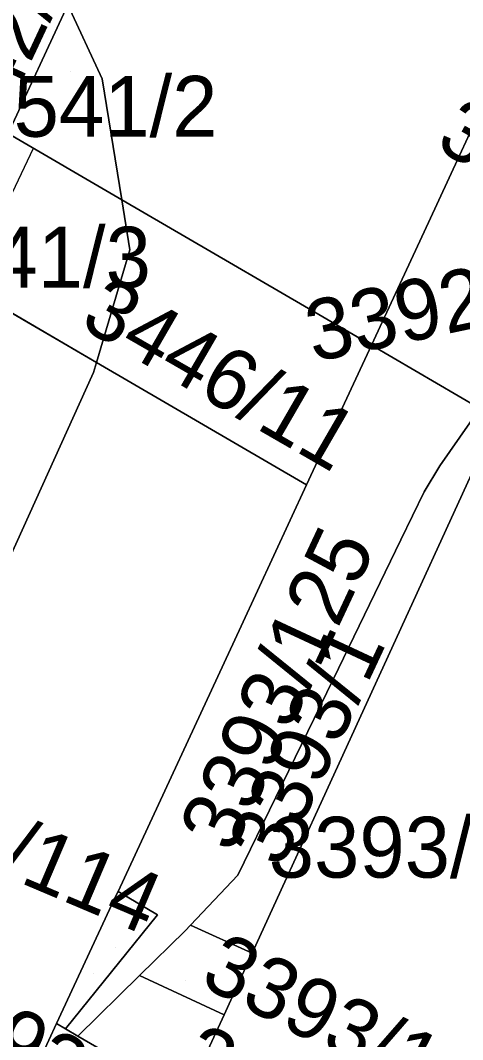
# Model space of a CAD drawing. Extents: x -262715 to -259381, y -1237238 to -1231182.
# Drawn here: x -261442.85 to -261428.34, y -1236026.92 to -1235993.4 of the extents above; entities that cross this region are included whole.
import ezdxf

# ---------------------------------------------------------------- set-up
doc = ezdxf.new("R2010")
doc.units = 0
for name, color, linetype in [('body_kn', 7, 'Continuous'), ('kladpar_druhypozemkov', 7, 'Continuous'), ('kladpar_hranice', 7, 'Continuous'), ('kladpar_parcelnecisla', 7, 'Continuous'), ('kladpar_plochy', 7, 'Continuous'), ('kladpar_sipky', 7, 'Continuous'), ('tarchy_linie', 7, 'Continuous')]:
    doc.layers.add(name, color=color, linetype=linetype)

msp = doc.modelspace()

# ---------------------------------------------------------------- linework, layer by layer
at = {"layer": 'body_kn'}
for p, q in [((-261440.17, -1235995.33), (-261440.17, -1235995.33)), ((-261442.42, -1235997.61), (-261442.42, -1235997.61)), ((-261439.53, -1235999.3), (-261439.53, -1235999.3)), ((-261439.53, -1235999.3), (-261439.53, -1235999.3)), ((-261429.46, -1236000.05), (-261429.46, -1236000.05)), ((-261429.46, -1236000.05), (-261429.46, -1236000.05)), ((-261439.26, -1236000.95), (-261439.26, -1236000.95)), ((-261431.33, -1236004.08), (-261431.33, -1236004.08)), ((-261431.33, -1236004.08), (-261431.33, -1236004.08)), ((-261440.36, -1236004.65), (-261440.36, -1236004.65)), ((-261440.36, -1236004.65), (-261440.36, -1236004.65)), ((-261440.46, -1236004.98), (-261440.46, -1236004.98)), ((-261429.08, -1236008.05), (-261429.08, -1236008.05)), ((-261433.46, -1236008.68), (-261433.46, -1236008.68)), ((-261433.46, -1236008.68), (-261433.46, -1236008.68)), ((-261429.6, -1236008.91), (-261429.6, -1236008.91)), ((-261430.36, -1236010.48), (-261430.36, -1236010.48)), ((-261435.61, -1236013.32), (-261435.61, -1236013.32)), ((-261435.61, -1236013.32), (-261435.61, -1236013.32)), ((-261432.59, -1236015.07), (-261432.59, -1236015.07)), ((-261435.72, -1236021.51), (-261435.72, -1236021.51)), ((-261439.71, -1236022.17), (-261439.71, -1236022.17)), ((-261439.65, -1236022.05), (-261439.65, -1236022.05)), ((-261438.35, -1236022.81), (-261438.35, -1236022.81)), ((-261437.27, -1236023.15), (-261437.27, -1236023.15)), ((-261437.27, -1236023.15), (-261437.27, -1236023.15)), ((-261437.45, -1236023.34), (-261437.45, -1236023.34)), ((-261435.25, -1236024.07), (-261435.25, -1236024.07)), ((-261438.95, -1236024.81), (-261438.95, -1236024.81)), ((-261438.95, -1236024.81), (-261438.95, -1236024.81)), ((-261436.17, -1236026.1), (-261436.17, -1236026.1)), ((-261441.67, -1236026.39), (-261441.67, -1236026.39)), ((-261441.67, -1236026.39), (-261441.67, -1236026.39)), ((-261441.38, -1236026.56), (-261441.38, -1236026.56)), ((-261441.38, -1236026.56), (-261441.38, -1236026.56)), ((-261440.97, -1236026.8), (-261440.97, -1236026.8))]:
    msp.add_line(p, q, dxfattribs=at)
at = {"layer": 'kladpar_druhypozemkov'}
for p, q in [((-261441.2, -1235995.07), (-261441.2, -1235995.07)), ((-261441.38, -1236000.2), (-261441.38, -1236000.2)), ((-261435.7, -1236004.53), (-261435.7, -1236004.53)), ((-261435.3, -1236015.31), (-261435.3, -1236015.31)), ((-261428.42, -1236020.41), (-261428.42, -1236020.41)), ((-261434.43, -1236021.08), (-261434.43, -1236021.08)), ((-261439.72, -1236023.9), (-261439.72, -1236023.9)), ((-261437.42, -1236024.97), (-261437.42, -1236024.97))]:
    msp.add_line(p, q, dxfattribs=at)
at = {"layer": 'kladpar_hranice'}
for p, q in [((-261443.26, -1235997.12), (-261441.3, -1235992.89)), ((-261441.3, -1235992.89), (-261443.26, -1235997.12)), ((-261429.46, -1236000.05), (-261427.15, -1235995.05)), ((-261439.53, -1235999.3), (-261443.26, -1235997.12)), ((-261443.26, -1235997.12), (-261439.53, -1235999.3)), ((-261439.53, -1235999.3), (-261431.33, -1236004.08)), ((-261431.33, -1236004.08), (-261439.53, -1235999.3)), ((-261431.33, -1236004.08), (-261429.46, -1236000.05)), ((-261440.36, -1236004.65), (-261445.39, -1236001.71)), ((-261445.39, -1236001.71), (-261440.36, -1236004.65)), ((-261431.33, -1236004.08), (-261433.46, -1236008.68)), ((-261431.33, -1236004.08), (-261427.77, -1236006.16)), ((-261427.77, -1236006.16), (-261431.33, -1236004.08)), ((-261440.36, -1236004.65), (-261433.46, -1236008.68)), ((-261433.46, -1236008.68), (-261440.36, -1236004.65))]:
    msp.add_line(p, q, dxfattribs=at)
for points in [[(-261439.53, -1235999.3), (-261440.17, -1235995.33), (-261441.3, -1235992.89), (-261437.51, -1235985.18), (-261436.1, -1235986.28), (-261433.77, -1235985.98), (-261432.39, -1235984.96), (-261430.91, -1235983.17), (-261428.74, -1235979.56), (-261421.41, -1235964.22), (-261426.16, -1235960.39), (-261419.45, -1235945.82), (-261410.92, -1235928.75)], [(-261401.46, -1235940.47), (-261403.81, -1235945.21), (-261406.09, -1235949.81), (-261407.58, -1235952.81), (-261408.21, -1235954.17), (-261410.37, -1235958.84), (-261411.71, -1235961.72), (-261412.83, -1235964.14), (-261414, -1235966.68), (-261416.49, -1235972.04), (-261418.71, -1235976.83), (-261419.79, -1235979.16), (-261419.99, -1235979.6), (-261421.22, -1235982.25), (-261422.36, -1235984.72), (-261423.67, -1235987.55), (-261424.98, -1235990.37), (-261427.15, -1235995.05), (-261429.46, -1236000.05), (-261431.33, -1236004.08)], [(-261441.3, -1235992.89), (-261440.17, -1235995.33), (-261439.53, -1235999.3)], [(-261440.36, -1236004.65), (-261439.26, -1236000.95), (-261439.53, -1235999.3)], [(-261439.53, -1235999.3), (-261439.26, -1236000.95), (-261440.36, -1236004.65)], [(-261435.61, -1236013.32), (-261433.46, -1236008.68), (-261431.33, -1236004.08)], [(-261489.43, -1236090.9), (-261486.64, -1236087.5), (-261485.82, -1236085.89), (-261476.25, -1236073.39), (-261474.75, -1236071.35), (-261462.25, -1236050.52), (-261450.96, -1236027.89), (-261448.42, -1236022.45), (-261447.68, -1236020.88), (-261446.76, -1236018.89), (-261446.57, -1236018.49), (-261446.4, -1236018.11), (-261440.46, -1236004.98), (-261440.36, -1236004.65)], [(-261440.36, -1236004.65), (-261440.46, -1236004.98), (-261446.4, -1236018.11)], [(-261427.77, -1236006.16), (-261429.08, -1236008.05), (-261429.6, -1236008.91), (-261430.36, -1236010.48), (-261432.59, -1236015.07), (-261435.72, -1236021.51), (-261437.27, -1236023.15), (-261437.45, -1236023.34), (-261438.95, -1236024.81), (-261440.97, -1236026.8), (-261441.38, -1236026.56), (-261438.35, -1236022.81), (-261439.65, -1236022.05), (-261435.61, -1236013.32)], [(-261437.27, -1236023.15), (-261435.72, -1236021.51), (-261432.59, -1236015.07), (-261430.36, -1236010.48), (-261429.6, -1236008.91), (-261429.08, -1236008.05), (-261427.77, -1236006.16)], [(-261417.64, -1236012.07), (-261418.09, -1236012.44), (-261418.6, -1236013.19), (-261419.04, -1236014.13), (-261420.29, -1236016.79), (-261420.45, -1236017.75), (-261426.15, -1236030.1), (-261426.62, -1236031.41), (-261426.78, -1236032.37), (-261426.94, -1236034.35), (-261426.92, -1236034.92), (-261431.39, -1236032.34), (-261437.43, -1236028.85), (-261436.17, -1236026.1), (-261435.25, -1236024.07), (-261427.39, -1236006.89)], [(-261422.8, -1236009.06), (-261422.88, -1236009.38), (-261427.39, -1236006.89), (-261435.25, -1236024.07), (-261437.27, -1236023.15)], [(-261433.46, -1236008.68), (-261435.61, -1236013.32), (-261439.65, -1236022.05), (-261439.71, -1236022.17), (-261441.67, -1236026.39), (-261442.68, -1236028.58), (-261443.81, -1236031.01), (-261445.84, -1236035.02), (-261451.51, -1236046.22), (-261456.63, -1236056.33), (-261465.66, -1236071.57), (-261466.87, -1236073.61), (-261468.88, -1236076.99), (-261477.58, -1236087.71), (-261480.44, -1236091.25), (-261483.14, -1236094.58)], [(-261441.38, -1236026.56), (-261441.67, -1236026.39), (-261439.71, -1236022.17), (-261439.65, -1236022.05), (-261438.35, -1236022.81), (-261441.38, -1236026.56)], [(-261438.95, -1236024.81), (-261437.45, -1236023.34), (-261437.27, -1236023.15), (-261435.25, -1236024.07), (-261436.17, -1236026.1), (-261438.95, -1236024.81)], [(-261438.95, -1236024.81), (-261436.17, -1236026.1), (-261437.43, -1236028.85), (-261440.97, -1236026.8), (-261438.95, -1236024.81)], [(-261441.67, -1236026.39), (-261441.38, -1236026.56), (-261440.97, -1236026.8), (-261437.43, -1236028.85), (-261438.45, -1236031.05), (-261442.68, -1236028.58), (-261441.67, -1236026.39)]]:
    msp.add_lwpolyline(points, dxfattribs=at)
at = {"layer": 'kladpar_plochy'}
for points in [[(-261441.3, -1235992.89), (-261443.26, -1235997.12), (-261445.84, -1235995.62), (-261443.03, -1235989.57)], [(-261441.3, -1235992.89), (-261440.17, -1235995.33), (-261439.53, -1235999.3), (-261443.26, -1235997.12)], [(-261443.26, -1235997.12), (-261439.53, -1235999.3), (-261439.26, -1236000.95), (-261440.36, -1236004.65), (-261445.39, -1236001.71)], [(-261431.33, -1236004.08), (-261433.46, -1236008.68), (-261440.36, -1236004.65), (-261439.26, -1236000.95), (-261439.53, -1235999.3)], [(-261440.36, -1236004.65), (-261440.46, -1236004.98), (-261446.4, -1236018.11), (-261451.6, -1236015.08), (-261445.39, -1236001.71)], [(-261435.61, -1236013.32), (-261433.46, -1236008.68), (-261431.33, -1236004.08), (-261427.77, -1236006.16), (-261429.08, -1236008.05), (-261429.6, -1236008.91), (-261430.36, -1236010.48), (-261432.59, -1236015.07), (-261435.72, -1236021.51), (-261437.27, -1236023.15), (-261437.45, -1236023.34), (-261438.95, -1236024.81), (-261440.97, -1236026.8), (-261441.38, -1236026.56), (-261438.35, -1236022.81), (-261439.65, -1236022.05)], [(-261437.27, -1236023.15), (-261435.72, -1236021.51), (-261432.59, -1236015.07), (-261430.36, -1236010.48), (-261429.6, -1236008.91), (-261429.08, -1236008.05), (-261427.77, -1236006.16), (-261422.8, -1236009.06), (-261422.88, -1236009.38), (-261427.39, -1236006.89), (-261435.25, -1236024.07)], [(-261427.39, -1236006.89), (-261422.88, -1236009.38), (-261422.8, -1236009.06), (-261417.64, -1236012.07), (-261418.09, -1236012.44), (-261418.6, -1236013.19), (-261419.04, -1236014.13), (-261420.29, -1236016.79), (-261420.45, -1236017.75), (-261426.15, -1236030.1), (-261426.62, -1236031.41), (-261426.78, -1236032.37), (-261426.94, -1236034.35), (-261426.92, -1236034.92), (-261431.39, -1236032.34), (-261437.43, -1236028.85), (-261436.17, -1236026.1), (-261435.25, -1236024.07)], [(-261441.38, -1236026.56), (-261441.67, -1236026.39), (-261439.71, -1236022.17), (-261439.65, -1236022.05), (-261438.35, -1236022.81)], [(-261438.95, -1236024.81), (-261437.45, -1236023.34), (-261437.27, -1236023.15), (-261435.25, -1236024.07), (-261436.17, -1236026.1)], [(-261438.95, -1236024.81), (-261436.17, -1236026.1), (-261437.43, -1236028.85), (-261440.97, -1236026.8)], [(-261441.67, -1236026.39), (-261441.38, -1236026.56), (-261440.97, -1236026.8), (-261437.43, -1236028.85), (-261438.45, -1236031.05), (-261442.68, -1236028.58)]]:
    msp.add_lwpolyline(points, close=True, dxfattribs=at)
for points in [[(-261424.98, -1235990.37), (-261427.15, -1235995.05), (-261429.46, -1236000.05), (-261431.33, -1236004.08), (-261439.53, -1235999.3), (-261440.17, -1235995.33), (-261441.3, -1235992.89)], [(-261427.77, -1236006.16), (-261431.33, -1236004.08), (-261429.46, -1236000.05), (-261427.15, -1235995.05)], [(-261462.25, -1236050.52), (-261450.96, -1236027.89), (-261448.42, -1236022.45), (-261447.68, -1236020.88), (-261446.76, -1236018.89), (-261446.57, -1236018.49), (-261446.4, -1236018.11), (-261440.46, -1236004.98), (-261440.36, -1236004.65), (-261433.46, -1236008.68), (-261435.61, -1236013.32), (-261439.65, -1236022.05), (-261439.71, -1236022.17), (-261441.67, -1236026.39), (-261442.68, -1236028.58), (-261443.81, -1236031.01), (-261445.84, -1236035.02), (-261451.51, -1236046.22)]]:
    msp.add_lwpolyline(points, dxfattribs=at)
at = {"layer": 'kladpar_sipky'}
for p, q in [((-261440.45, -1236024.73), (-261440.45, -1236024.73)), ((-261436.69, -1236024.86), (-261436.69, -1236024.86))]:
    msp.add_line(p, q, dxfattribs=at)
at = {"layer": 'tarchy_linie'}
msp.add_line((-261444.6, -1236002.17), (-261442.42, -1235997.61), dxfattribs=at)

# ---------------------------------------------------------------- texts
at = {"layer": 'kladpar_parcelnecisla'}
for s, rotation, p in [('3542/2', 65, (-261444.423, -1235998.888)), ('3393/91', 331, (-261429.286, -1235997.59)), ('3392/251', 12, (-261433.236, -1236004.649)), ('3446/11', 330, (-261440.962, -1236003.454)), ('3393/125', 65, (-261435.896, -1236020.834)), ('3393/1', 65, (-261434.3, -1236021.325)), ('3393/114', 337, (-261449.077, -1236019.122)), ('3393/130', 333, (-261437.019, -1236025.099)), ('3393/52', 330, (-261446.571, -1236025.971)), ('3393/66', 334, (-261437.752, -1236028.123))]:
    msp.add_text(s, height=2, rotation=rotation, dxfattribs=at).set_placement(p)
for s, p in [('3541/2', (-261444.565, -1235997.23)), ('3541/3', (-261446.75, -1236002.19)), ('3393/67', (-261434.701, -1236021.59))]:
    msp.add_text(s, height=2, dxfattribs=at).set_placement(p)

doc.saveas('drawing.dxf')
